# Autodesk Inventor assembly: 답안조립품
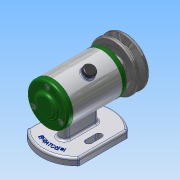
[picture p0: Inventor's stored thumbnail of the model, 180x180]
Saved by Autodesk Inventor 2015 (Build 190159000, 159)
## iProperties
Created: 2022-02
Part Number: 답안조립품
Document SubType Name: Assembly
Designer: 학생용
Author: 학생용
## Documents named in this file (14)
- C:\Users\학생용\Desktop\720206V1007\답안조립품.iam
- C:\Users\학생용\Desktop\720206V1007\V벨트풀리.ipt
- C:\Users\학생용\Desktop\720206V1007\고무 캡.ipt
- C:\Users\학생용\Desktop\720206V1007\너트 M8.ipt
- C:\Users\학생용\Desktop\720206V1007\뒤커버.ipt
- C:\Users\학생용\Desktop\720206V1007\베어링 6002.ipt
- C:\Users\학생용\Desktop\720206V1007\본체.ipt
- C:\Users\학생용\Desktop\720206V1007\볼트 M4 x 10.ipt
- C:\Users\학생용\Desktop\720206V1007\스프링와셔 8.ipt
- C:\Users\학생용\Desktop\720206V1007\앞커버.ipt
- C:\Users\학생용\Desktop\720206V1007\오일 실 15 x 25 x 7.ipt
- C:\Users\학생용\Desktop\720206V1007\축.ipt
- C:\Users\학생용\Desktop\720206V1007\키 3 x 3 x 12.ipt
- C:\Users\학생용\Desktop\720206V1007\평와셔 8 x 17.ipt
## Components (2 placed, 2 different names)
1. V벨트풀리:1
2. 고무 캡:1
